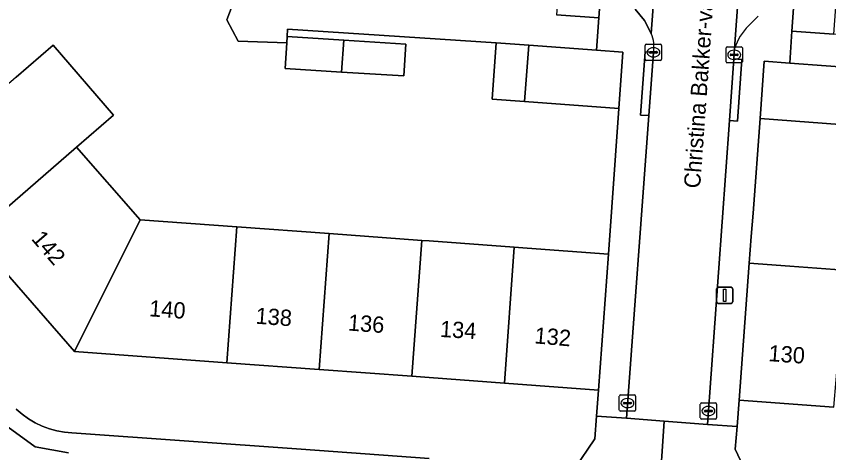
# Model space of a CAD drawing. Extents: x 160304 to 160955, y 383684 to 384161.
# Drawn here: x 160474.6 to 160524.56, y 383922.31 to 383949.15 of the extents above; entities that cross this region are included whole.
import ezdxf

# ---------------------------------------------------------------- set-up
doc = ezdxf.new("R2010")
doc.units = 0
for name, color, linetype in [('IMGEO_Erf', 7, 'Continuous'), ('IMGEO_Kolk', 7, 'Continuous'), ('IMGEO_Lichtmast', 7, 'Continuous'), ('IMGEO_Muur', 7, 'Continuous'), ('IMGEO_Openbare_ruimte_label', 7, 'Continuous'), ('IMGEO_Pand', 7, 'Continuous'), ('IMGEO_Pand_nummerreeks', 7, 'Continuous'), ('IMGEO_Parkeervlak_open', 7, 'Continuous'), ('IMGEO_Rijbaan_lokaal_open', 7, 'Continuous'), ('IMGEO_Voetpad_open', 7, 'Continuous')]:
    doc.layers.add(name, color=color, linetype=linetype)

msp = doc.modelspace()

# ---------------------------------------------------------------- linework, layer by layer
at = {"layer": 'IMGEO_Erf'}
for points in [[(160514.187, 384000), (160514.205, 384000.248), (160511.589, 384000.441), (160511.557, 384000), (160511.181, 383994.892), (160510.762, 383989.202), (160510.343, 383983.504), (160509.925, 383977.831), (160509.508, 383972.165), (160509.089, 383966.47), (160508.671, 383960.787), (160508.253, 383955.106), (160507.821, 383949.239), (160510.426, 383949.047)], [(160527.389, 383982.34), (160527.806, 383988.006), (160528.225, 383993.695), (160528.645, 383999.401), (160525.998, 383999.592), (160522.302, 383948.238), (160524.866, 383948.053), (160525.298, 383953.917), (160525.715, 383959.593), (160526.134, 383965.285), (160526.553, 383970.972), (160526.971, 383976.651)]]:
    msp.add_lwpolyline(points, close=True, dxfattribs=at)
for points in [[(160474.591, 383945.405), (160476.867, 383947.372), (160480.585, 383943.069), (160478.309, 383941.103), (160482.216, 383936.632), (160488.158, 383936.199), (160493.848, 383935.783), (160499.538, 383935.368), (160500, 383935.334), (160505.217, 383934.953), (160506.023, 383934.894), (160511.009, 383934.527), (160511.647, 383943.484), (160505.862, 383943.91), (160503.864, 383944.057), (160504.118, 383947.508), (160491.284, 383948.358), (160491.255, 383947.893), (160494.735, 383947.675), (160498.549, 383947.436), (160498.426, 383945.477), (160494.589, 383945.718), (160491.132, 383945.934), (160491.231, 383947.515), (160488.25, 383947.606), (160487.538, 383948.928), (160488.135, 383950.497)], [(160526.336, 383942.417), (160520.34, 383942.858), (160519.906, 383937.041), (160519.798, 383935.598), (160519.677, 383933.96), (160522.164, 383933.777), (160525.488, 383933.533)], [(160508.919, 383921.318), (160510.17, 383923.18), (160510.274, 383924.568), (160510.393, 383926.169), (160504.615, 383926.594), (160500, 383926.934), (160498.915, 383927.014), (160493.225, 383927.433), (160487.542, 383927.851), (160478.172, 383928.541), (160471.997, 383935.625)], [(160524.883, 383925.122), (160519.059, 383925.551), (160518.927, 383923.923), (160518.814, 383922.53), (160519.759, 383920.534), (160564.54, 383917.241)], [(160474.591, 383925.003), (160474.954, 383924.689), (160475.343, 383924.408), (160475.756, 383924.163), (160476.189, 383923.957), (160476.639, 383923.789), (160477.102, 383923.663), (160477.574, 383923.578), (160478.012, 383923.538), (160492.124, 383922.525), (160500, 383921.959)]]:
    msp.add_lwpolyline(points, dxfattribs=at)
at = {"layer": 'IMGEO_Kolk'}
for p, q in [((160513.279, 383946.501), (160513.279, 383947.353)), ((160513.354, 383947.427), (160514.206, 383947.427)), ((160514.28, 383947.353), (160514.28, 383946.501)), ((160513.538, 383946.921), (160513.538, 383946.933)), ((160513.976, 383946.884), (160513.578, 383946.884)), ((160513.581, 383946.97), (160513.979, 383946.97)), ((160513.767, 383947.207), (160513.792, 383947.207)), ((160514.022, 383946.933), (160514.022, 383946.921)), ((160518.247, 383946.346), (160518.247, 383947.198)), ((160518.322, 383947.272), (160519.174, 383947.272)), ((160518.549, 383946.815), (160518.947, 383946.815)), ((160518.735, 383947.052), (160518.76, 383947.052)), ((160519.248, 383947.198), (160519.248, 383946.346)), ((160514.206, 383946.427), (160513.354, 383946.427)), ((160513.79, 383946.647), (160513.765, 383946.647)), ((160518.506, 383946.766), (160518.506, 383946.778)), ((160518.944, 383946.729), (160518.546, 383946.729)), ((160518.758, 383946.492), (160518.733, 383946.492)), ((160518.99, 383946.778), (160518.99, 383946.766)), ((160519.174, 383946.272), (160518.322, 383946.272)), ((160511.759, 383925.868), (160512.611, 383925.868)), ((160511.684, 383924.942), (160511.684, 383925.794)), ((160511.943, 383925.362), (160511.943, 383925.374)), ((160512.381, 383925.325), (160511.983, 383925.325)), ((160511.986, 383925.411), (160512.384, 383925.411)), ((160512.172, 383925.648), (160512.197, 383925.648)), ((160512.427, 383925.374), (160512.427, 383925.362)), ((160512.685, 383925.794), (160512.685, 383924.942)), ((160516.74, 383925.379), (160517.592, 383925.379)), ((160512.611, 383924.868), (160511.759, 383924.868)), ((160512.195, 383925.088), (160512.17, 383925.088)), ((160516.665, 383924.453), (160516.665, 383925.305)), ((160516.924, 383924.873), (160516.924, 383924.885)), ((160517.362, 383924.836), (160516.964, 383924.836)), ((160516.967, 383924.922), (160517.365, 383924.922)), ((160517.153, 383925.159), (160517.178, 383925.159)), ((160517.408, 383924.885), (160517.408, 383924.873)), ((160517.666, 383925.305), (160517.666, 383924.453)), ((160517.592, 383924.379), (160516.74, 383924.379)), ((160517.176, 383924.599), (160517.151, 383924.599))]:
    msp.add_line(p, q, dxfattribs=at)
for points in [[(160513.279, 383946.501), (160513.279, 383947.353)], [(160513.354, 383947.427), (160514.206, 383947.427)], [(160514.28, 383947.353), (160514.28, 383946.501)], [(160518.247, 383946.346), (160518.247, 383947.198)], [(160518.322, 383947.272), (160519.174, 383947.272)], [(160519.248, 383947.198), (160519.248, 383946.346)], [(160514.206, 383946.427), (160513.354, 383946.427)], [(160519.174, 383946.272), (160518.322, 383946.272)], [(160511.759, 383925.868), (160512.611, 383925.868)], [(160511.684, 383924.942), (160511.684, 383925.794)], [(160512.685, 383925.794), (160512.685, 383924.942)], [(160516.74, 383925.379), (160517.592, 383925.379)], [(160512.611, 383924.868), (160511.759, 383924.868)], [(160516.665, 383924.453), (160516.665, 383925.305)], [(160517.666, 383925.305), (160517.666, 383924.453)], [(160517.592, 383924.379), (160516.74, 383924.379)]]:
    msp.add_lwpolyline(points, dxfattribs=at)
for centre, radius, start, end in [((160513.356, 383947.351), 0.0765, 91.552, 178.448), ((160513.356, 383947.351), 0.0765, 91.552, 178.448), ((160514.204, 383947.351), 0.0765, 1.552, 88.448), ((160514.204, 383947.351), 0.0765, 1.552, 88.448), ((160513.578, 383946.93), 0.0403, 85.8775, 175.7526), ((160513.575, 383946.92), 0.0366, 178.938, 274.7102), ((160513.979, 383946.927), 0.043, 264.8664, 352.4533), ((160513.983, 383946.932), 0.0386, 1.7309, 96.639), ((160518.324, 383947.196), 0.0765, 91.552, 178.448), ((160518.324, 383947.196), 0.0765, 91.552, 178.448), ((160518.546, 383946.775), 0.0403, 85.8775, 175.7526), ((160518.951, 383946.777), 0.0386, 1.7309, 96.639), ((160519.172, 383947.196), 0.0765, 1.552, 88.448), ((160519.172, 383947.196), 0.0765, 1.552, 88.448), ((160513.356, 383946.503), 0.0765, 181.552, 268.448), ((160513.356, 383946.503), 0.0765, 181.552, 268.448), ((160514.204, 383946.503), 0.0765, 271.552, 358.448), ((160514.204, 383946.503), 0.0765, 271.552, 358.448), ((160518.324, 383946.348), 0.0765, 181.552, 268.448), ((160518.324, 383946.348), 0.0765, 181.552, 268.448), ((160518.543, 383946.765), 0.0366, 178.938, 274.7102), ((160518.947, 383946.772), 0.043, 264.8664, 352.4533), ((160519.172, 383946.348), 0.0765, 271.552, 358.448), ((160519.172, 383946.348), 0.0765, 271.552, 358.448), ((160511.761, 383925.792), 0.0765, 91.552, 178.448), ((160511.761, 383925.792), 0.0765, 91.552, 178.448), ((160512.609, 383925.792), 0.0765, 1.552, 88.448), ((160512.609, 383925.792), 0.0765, 1.552, 88.448), ((160511.983, 383925.371), 0.0403, 85.8775, 175.7526), ((160511.98, 383925.361), 0.0366, 178.938, 274.7102), ((160512.384, 383925.368), 0.043, 264.8664, 352.4533), ((160512.388, 383925.373), 0.0386, 1.7309, 96.639), ((160516.742, 383925.303), 0.0765, 91.552, 178.448), ((160516.742, 383925.303), 0.0765, 91.552, 178.448), ((160517.59, 383925.303), 0.0765, 1.552, 88.448), ((160517.59, 383925.303), 0.0765, 1.552, 88.448), ((160511.761, 383924.944), 0.0765, 181.552, 268.448), ((160511.761, 383924.944), 0.0765, 181.552, 268.448), ((160512.609, 383924.944), 0.0765, 271.552, 358.448), ((160512.609, 383924.944), 0.0765, 271.552, 358.448), ((160516.964, 383924.882), 0.0403, 85.8775, 175.7526), ((160516.961, 383924.872), 0.0366, 178.938, 274.7102), ((160517.365, 383924.879), 0.043, 264.8664, 352.4533), ((160517.369, 383924.884), 0.0386, 1.7309, 96.639), ((160516.742, 383924.455), 0.0765, 181.552, 268.448), ((160516.742, 383924.455), 0.0765, 181.552, 268.448), ((160517.59, 383924.455), 0.0765, 271.552, 358.448), ((160517.59, 383924.455), 0.0765, 271.552, 358.448)]:
    msp.add_arc(centre, radius, start, end, dxfattribs=at)
for centre, major_axis, ratio, start_param, end_param in [((160513.766, 383946.927), (-0.387, 0.002), 0.722429, 4.712389, 7.853982), ((160513.791, 383946.927), (-0.39, 0.002), 0.717154, 1.570796, 4.712389), ((160518.734, 383946.772), (-0.387, 0.002), 0.722429, 4.712389, 7.853982), ((160518.759, 383946.772), (-0.39, 0.002), 0.717154, 1.570796, 4.712389), ((160512.171, 383925.368), (-0.387, 0.002), 0.722429, 4.712389, 7.853982), ((160512.196, 383925.368), (-0.39, 0.002), 0.717154, 1.570796, 4.712389), ((160517.152, 383924.879), (-0.387, 0.002), 0.722429, 4.712389, 7.853982), ((160517.177, 383924.879), (-0.39, 0.002), 0.717154, 1.570796, 4.712389)]:
    msp.add_ellipse(centre, major_axis=major_axis, ratio=ratio, start_param=start_param, end_param=end_param, dxfattribs=at)
at = {"layer": 'IMGEO_Lichtmast'}
for p, q in [((160517.668, 383931.591), (160517.668, 383932.391)), ((160517.668, 383932.391), (160517.668, 383931.591)), ((160517.768, 383932.491), (160518.558, 383932.491)), ((160518.558, 383932.491), (160517.768, 383932.491)), ((160518.658, 383932.391), (160518.658, 383931.591)), ((160518.658, 383931.591), (160518.658, 383932.391)), ((160518.558, 383931.491), (160517.768, 383931.491)), ((160517.768, 383931.491), (160518.558, 383931.491))]:
    msp.add_line(p, q, dxfattribs=at)
msp.add_lwpolyline([(160518.088, 383932.366), (160518.238, 383932.366), (160518.238, 383931.616), (160518.088, 383931.616), (160518.088, 383932.366)], dxfattribs=at)
for centre, start, end in [((160517.768, 383932.391), 90, 180), ((160517.768, 383932.391), 90, 180), ((160518.558, 383932.391), 0, 90), ((160518.558, 383932.391), 360, 90), ((160517.768, 383931.591), 180, 270), ((160517.768, 383931.591), 180, 270), ((160518.558, 383931.591), 270, 0), ((160518.558, 383931.591), 270, 0)]:
    msp.add_arc(centre, 0.1, start, end, dxfattribs=at)
at = {"layer": 'IMGEO_Muur'}
for points in [[(160519.906, 383937.041), (160520.34, 383942.858)], [(160519.798, 383935.598), (160519.906, 383937.041)], [(160519.798, 383935.598), (160519.677, 383933.96)]]:
    msp.add_lwpolyline(points, dxfattribs=at)
at = {"layer": 'IMGEO_Pand'}
for points in [[(160494.735, 383947.675), (160491.255, 383947.893), (160491.231, 383947.515), (160491.132, 383945.934), (160494.589, 383945.718)], [(160468.271, 383939.938), (160471.997, 383935.625), (160478.309, 383941.103), (160480.585, 383943.069), (160476.867, 383947.372), (160474.591, 383945.405)], [(160494.589, 383945.718), (160498.426, 383945.477), (160498.549, 383947.436), (160494.735, 383947.675)], [(160505.862, 383943.91), (160506.111, 383947.361), (160504.118, 383947.508), (160503.864, 383944.057)], [(160505.862, 383943.91), (160511.647, 383943.484), (160511.901, 383946.936), (160510.279, 383947.055), (160506.111, 383947.361)], [(160526.632, 383945.941), (160522.16, 383946.27), (160520.599, 383946.385), (160520.34, 383942.858), (160526.336, 383942.417)], [(160471.997, 383935.625), (160478.172, 383928.541), (160482.216, 383936.632), (160478.309, 383941.103)], [(160487.542, 383927.851), (160488.158, 383936.199), (160482.216, 383936.632), (160478.172, 383928.541)], [(160493.848, 383935.783), (160488.158, 383936.199), (160487.542, 383927.851), (160493.225, 383927.433)], [(160493.848, 383935.783), (160493.225, 383927.433), (160498.915, 383927.014), (160499.538, 383935.368)], [(160498.915, 383927.014), (160500, 383926.934), (160504.615, 383926.594), (160505.217, 383934.953), (160500, 383935.334), (160499.538, 383935.368)], [(160505.217, 383934.953), (160504.615, 383926.594), (160510.393, 383926.169), (160511.009, 383934.527), (160506.023, 383934.894)], [(160522.164, 383933.777), (160519.677, 383933.96), (160519.059, 383925.551), (160524.883, 383925.122), (160525.589, 383933.526), (160525.488, 383933.533)]]:
    msp.add_lwpolyline(points, close=True, dxfattribs=at)
at = {"layer": 'IMGEO_Parkeervlak_open'}
for points in [[(160512.668, 383949.583), (160513.226, 383948.884), (160513.645, 383948.079), (160515.611, 383974.485), (160515.815, 383977.238), (160516.629, 383988.167), (160517.469, 384000), (160517.587, 384001.661)], [(160523.692, 383998.016), (160522.497, 383999.449), (160521.51, 383984.995), (160520.923, 383976.868), (160520.723, 383974.115), (160518.776, 383947.168)], [(160519.624, 383948.562), (160520.222, 383949.145)]]:
    msp.add_lwpolyline(points, dxfattribs=at)
msp.add_arc((160522.265, 383946), 3.679, 135.8766, 161.4973, dxfattribs=at)
at = {"layer": 'IMGEO_Rijbaan_lokaal_open'}
for points in [[(160513.781, 383946.923), (160513.493, 383943.035), (160512.117, 383924.431), (160514.451, 383924.257), (160517.105, 383924.059), (160518.455, 383942.738), (160518.729, 383946.518), (160518.776, 383947.168), (160520.723, 383974.115), (160515.611, 383974.485), (160513.645, 383948.079)], [(160477.817, 383922.307), (160475.762, 383922.669), (160473.647, 383924.212), (160454.45, 383946.404), (160454.071, 383946.797), (160453.657, 383947.154), (160453.214, 383947.473), (160452.744, 383947.75), (160452.251, 383947.985), (160451.739, 383948.175), (160451.212, 383948.319), (160451.028, 383948.357), (160450.116, 383948.792), (160450.007, 383948.842), (160449.625, 383949.047), (160449.263, 383949.284), (160448.923, 383949.553), (160448.609, 383949.851), (160442.881, 383956.488), (160440.439, 383954.379), (160442.745, 383951.711), (160446.96, 383946.834)]]:
    msp.add_lwpolyline(points, dxfattribs=at)
msp.add_arc((160511.924, 383947.29), 1.893, 348.8089, 24.6108, dxfattribs=at)
at = {"layer": 'IMGEO_Voetpad_open'}
for points in [[(160518.776, 383947.168), (160518.729, 383946.518), (160519.227, 383946.483), (160518.953, 383942.703), (160518.455, 383942.738), (160517.105, 383924.059), (160518.927, 383923.923), (160519.059, 383925.551), (160519.677, 383933.96), (160519.798, 383935.598), (160519.906, 383937.041), (160520.34, 383942.858), (160520.599, 383946.385), (160522.16, 383946.27), (160522.302, 383948.238), (160525.998, 383999.592), (160526.027, 384000), (160526.157, 384001.805), (160526.404, 384005.17), (160524.792, 384005.245), (160525.428, 384014.213), (160526.037, 384022.511), (160526.375, 384026.574)], [(160514.365, 384002.417), (160514.205, 384000.248), (160514.187, 384000), (160510.426, 383949.047), (160510.279, 383947.055), (160511.901, 383946.936), (160511.647, 383943.484), (160511.009, 383934.527), (160510.393, 383926.169), (160510.274, 383924.568), (160512.117, 383924.431), (160513.493, 383943.035), (160512.995, 383943.072), (160513.283, 383946.96), (160513.781, 383946.923)], [(160488.135, 383950.497), (160487.538, 383948.928), (160488.25, 383947.606), (160491.231, 383947.515), (160491.255, 383947.893), (160491.284, 383948.358), (160504.118, 383947.508), (160506.111, 383947.361), (160510.279, 383947.055), (160510.426, 383949.047), (160507.821, 383949.239)], [(160513.645, 383948.079), (160513.226, 383948.884), (160512.668, 383949.583)], [(160520.222, 383949.145), (160519.624, 383948.562)], [(160500, 383921.959), (160492.124, 383922.525), (160478.012, 383923.538), (160477.574, 383923.578), (160477.102, 383923.663), (160476.639, 383923.789), (160476.189, 383923.957), (160475.756, 383924.163), (160475.343, 383924.408), (160474.954, 383924.689), (160474.591, 383925.003)], [(160514.136, 383919.672), (160514.451, 383924.257), (160512.117, 383924.431), (160510.274, 383924.568), (160510.17, 383923.18), (160508.919, 383921.318)], [(160473.647, 383924.212), (160475.762, 383922.669), (160477.817, 383922.307)], [(160564.54, 383917.241), (160519.759, 383920.534), (160518.814, 383922.53), (160518.927, 383923.923), (160517.105, 383924.059), (160514.451, 383924.257), (160514.136, 383919.672), (160545.126, 383917.424)]]:
    msp.add_lwpolyline(points, dxfattribs=at)
for points in [[(160545.059, 383947.785), (160546.837, 383950.635), (160548.795, 383954.127), (160550.574, 383957.238), (160549.244, 383957.994), (160547.457, 383954.868), (160545.615, 383951.492), (160546.067, 383951.245), (160544.251, 383947.916), (160543.641, 383948.249), (160542.815, 383946.734), (160533.149, 383947.444), (160529.853, 383947.686), (160524.866, 383948.053), (160522.302, 383948.238), (160522.16, 383946.27), (160526.632, 383945.941), (160528.267, 383945.821), (160543.152, 383944.729)], [(160513.493, 383943.035), (160513.781, 383946.923), (160513.283, 383946.96), (160512.995, 383943.072)], [(160518.729, 383946.518), (160518.455, 383942.738), (160518.953, 383942.703), (160519.227, 383946.483)]]:
    msp.add_lwpolyline(points, close=True, dxfattribs=at)
for centre, radius, start, end in [((160522.265, 383946), 3.679, 135.8766, 161.4973), ((160511.924, 383947.29), 1.893, 348.8089, 24.6108)]:
    msp.add_arc(centre, radius, start, end, dxfattribs=at)

# ---------------------------------------------------------------- texts
at = {"layer": 'IMGEO_Openbare_ruimte_label'}
msp.add_text('Christina Bakker-van Bossestraat', height=1, rotation=85.8695, dxfattribs=at).set_placement((160516.647, 383938.543))
at = {"layer": 'IMGEO_Pand_nummerreeks'}
for s, rotation, p in [('142', 310.8221, (160475.484, 383935.442)), ('140', 355.7903, (160482.747, 383930.706)), ('138', 355.7903, (160489.29, 383930.25)), ('136', 355.7903, (160494.971, 383929.831)), ('134', 356.5508, (160500.634, 383929.435)), ('132', 355.0401, (160506.439, 383929.042)), ('130', 355.7913, (160520.832, 383927.948))]:
    msp.add_text(s, height=1, rotation=rotation, dxfattribs=at).set_placement(p)

doc.saveas('drawing.dxf')
